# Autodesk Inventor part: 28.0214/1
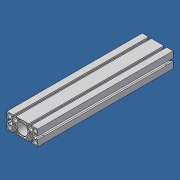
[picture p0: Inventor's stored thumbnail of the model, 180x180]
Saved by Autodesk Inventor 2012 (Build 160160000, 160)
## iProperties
Created: 2011-05
Part Number: 28.0214/1
Material: Aluminum-6061
Description: L = TRAVEL + 3.543" MACHINE TO PRINT 28.0214/1
Document SubType Name: Modeling
Designer: Administrator
Stock Number: 20.1017 PROFILE 45X90 S
Density: 2.71 g/cm^3
Vendor: F
FINISH: CLEAR ANODIZED
Author: Administrator
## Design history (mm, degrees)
sketch "Sketch1"
  geometry: L1 (11.7, 20.5)-(11.7, 15.701) reference; L2 (-11.7, 15.701)-(-11.7, 20.5) reference; L3 (-11.7, 20.5)-(11.7, 20.5) reference; L4 (-11.7, -20.5)-(-11.7, -15.701) reference; L5 (11.7, -15.701)-(11.7, -20.5) reference; L6 (11.7, -20.5)-(-11.7, -20.5) reference; L7 (26.6, 22.5)-(26.6, 18) reference; L8 (27.1, 18)-(29.3, 18) reference; L9 (29.3, 18)-(29.3, 9.5) reference; L10 (29.3, 9.5)-(27, 7.2) reference; L11 (27, 7.2)-(18, 7.2) reference; L12 (18, 7.2)-(15.7, 9.5) reference; L13 (15.7, 9.5)-(15.7, 18) reference; L14 (18.4, 18)-(18.4, 22.5) reference; L15 (-18.4, 22.5)-(-18.4, 18) reference; L16 (-15.7, 18)-(-15.7, 9.5) reference; L17 (-15.7, 9.5)-(-18, 7.2) reference; L18 (-18, 7.2)-(-27, 7.2) reference; L19 (-27, 7.2)-(-29.3, 9.5) reference; L20 (-29.3, 9.5)-(-29.3, 18) reference; L21 (-29.3, 18)-(-27.1, 18) reference; L22 (-26.6, 18)-(-26.6, 22.5) reference; L23 (-45, 4.1)-(-40.5, 4.1) reference; L24 (-40.5, 6.8)-(-32, 6.8) reference; L25 (-32, 6.8)-(-29.7, 4.5) reference; L26 (-29.7, 4.5)-(-29.7, -4.5) reference; L27 (-29.7, -4.5)-(-32, -6.8) reference; L28 (-32, -6.8)-(-40.5, -6.8) reference; L29 (-40.5, -6.8)-(-40.5, -4.6) reference; L30 (-40.5, -4.1)-(-45, -4.1) reference; L31 (-45, -22.5)-(-45, -4.4) reference; L32 (-26.6, -22.5)-(-26.6, -18) reference; L33 (-27.1, -18)-(-29.3, -18) reference; L34 (-29.3, -18)-(-29.3, -9.5) reference; L35 (-29.3, -9.5)-(-27, -7.2) reference; L36 (-27, -7.2)-(-18, -7.2) reference; L37 (-18, -7.2)-(-15.7, -9.5) reference; L38 (-15.7, -9.5)-(-15.7, -18) reference; L39 (-18.4, -18)-(-18.4, -22.5) reference; L40 (18.4, -22.5)-(18.4, -18) reference; L41 (15.7, -18)-(15.7, -9.5) reference; L42 (15.7, -9.5)-(18, -7.2) reference; L43 (18, -7.2)-(27, -7.2) reference; L44 (27, -7.2)-(29.3, -9.5) reference; L45 (29.3, -9.5)-(29.3, -18) reference; L46 (29.3, -18)-(27.1, -18) reference; L47 (26.6, -18)-(26.6, -22.5) reference; L48 (45, -22.5)-(26.9, -22.5) reference; L49 (45, -4.4)-(45, -22.5) reference; L50 (45, -4.1)-(40.5, -4.1) reference; L51 (40.5, -4.6)-(40.5, -6.8) reference; L52 (40.5, -6.8)-(32, -6.8) reference; L53 (32, -6.8)-(29.7, -4.5) reference; L54 (29.7, -4.5)-(29.7, 4.5) reference; L55 (29.7, 4.5)-(32, 6.8) reference; L56 (32, 6.8)-(40.5, 6.8) reference; L57 (40.5, 4.1)-(45, 4.1) reference; L58 (26.9, 22.5)-(45, 22.5) reference; L59 (-45, -4.4)-(-45, -4.1) reference; L60 (-45, 4.1)-(-45, 22.5) reference; L61 (-40.5, -4.6)-(-40.5, -4.1) reference; L62 (-40.5, 4.1)-(-40.5, 6.8) reference; L63 (-27.1, 18)-(-26.6, 18) reference; L64 (-18.4, 18)-(-15.7, 18) reference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; C1 r 3.75 at (22.5, 0) reference; C2 r 3.75 at (-22.5, 0) reference; C3 r 16 at (0, 0) reference; C4 r 5.85 at (-37.15, -14.65) reference; C5 r 5.85 at (-37.15, 14.65) reference; C6 r 5.85 at (37.15, -14.65) reference; C7 r 5.85 at (37.15, 14.65) reference; A1 r 1 centre (10.7, 15.701) between (10.137, 14.874) and (11.7, 15.701) reference; A2 r 18 centre (0, 0) between (10.137, 14.874) and (-10.137, 14.874) reference; A3 r 1 centre (-10.7, 15.701) between (-11.7, 15.701) and (-10.137, 14.874) reference; A4 r 1 centre (-10.7, -15.701) between (-10.137, -14.874) and (-11.7, -15.701) reference; A5 r 18 centre (0, 0) between (-10.137, -14.874) and (10.137, -14.874) reference; A6 r 1 centre (10.7, -15.701) between (11.7, -15.701) and (10.137, -14.874) reference
  constraints: 164 end point, 36 horizontal, 34 vertical, 13 centre point, 12 point on circle, 126 other
extrude "Extrusion1" new body sketch "Sketch1" stored distance "d0" = 394.8 (computed from TRAVEL); taper "d1" = 0 deg
sketch "Sketch2"
  geometry: L1 (0, 18.4)-(0, 0) reference; L2 (394.8, 0)-(394.8, 18.4) reference; L3 (394.8, -8.6)-(394.8, 0.4) reference; L4 (0, 0.4)-(0, -8.6) reference; L5 (20, 0.65)-(374.8, 0.65); L6 (374.8, -8.85)-(20, -8.85); A1 r 4.75 centre (20, -4.1) between (20, 0.65) and (20, -8.85); A2 r 4.75 centre (374.8, -4.1) between (374.8, -8.85) and (374.8, 0.65); 3 further points
  constraints: 4 end point, 4 point on circle, 4 tangent, 2 centre point, 2 horizontal alignment, 2 midpoint, 1 equal radius
  dimensions: "d2" = 20 distance from line of A1.centre L1 (= d3); "d3" = 20 distance from line of A2.centre L2; "d4" = 4.75 radius of A2
extrude "Extrusion2" cut sketch "Sketch2" distance "d5" = 31.75; taper "d6" = 0 deg
thread "Thread1" dims "d7" = 25.4, "d8" = 369.316
thread "Thread2" dims "d9" = 25.4, "d10" = 0
thread "Thread3" dims "d11" = 25.4, "d12" = 0
thread "Thread4" dims "d13" = 25.4, "d14" = 0
body "Solid1"
other parameters: "TRAVEL" = 304.8 [user parameter; used in 1 equation term]
